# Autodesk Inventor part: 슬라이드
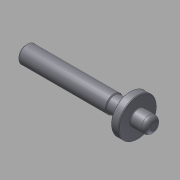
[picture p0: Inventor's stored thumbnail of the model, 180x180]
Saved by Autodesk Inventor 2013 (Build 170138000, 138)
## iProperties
Company: 한국ATC센터
Created: 2015-12
Part Number: 슬라이드
Document SubType Name: Modeling
Designer: mdu
Density: 7.86 g/cm^3
Mass: 68.0563 g
Surface Area: 34.7349 cm^2
Volume: 8.65856 cm^3
Material: 강철, 연강
Author: mdu
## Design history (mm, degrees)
sketch "스케치1"
  geometry: L1 (-35, 0)-(35, 0); L2 (35, 0)-(35, 12); L3 (35, 12)-(30, 12); L4 (30, 12)-(30, 5); L5 (30, 5)-(20.5, 5); L6 (20.5, 5)-(20, 5.5); L7 (20, 5.5)-(-35, 5.5); L8 (-35, 5.5)-(-35, 0); 1 further point
  constraints: 16 end point, 4 parallel, 2 midpoint, 2 perpendicular, 1 horizontal
  dimensions: "d0" = 70 distance of L1.start L1.end; "d1" = 11 diameter of L7 L1; "d2" = 24 diameter of L3 L1; "d3" = 5 distance of L2.end L3.end; "d4" = 10 diameter of L5 L1; "d5" = 135 deg angle of L6 L5; "d6" = 15 distance from line of L2 L6.end
revolve "회전1" sketch "스케치1" stored, may be unused: angle "d7" = 90 deg
chamfer "모따기1" distance "d8" = 1; stored, may be unused: second distance "d9" = 2, angle "d10" = 45 deg
fillet "모깎기1" dims "d11" = 0.5
sketch "스케치2"
  geometry: C1 r 11.5 at (0, 0) reference; C2 r 5 at (0, 0)
  constraints: 1 centre point, 1 coincident
  dimensions: "d12" = 10 diameter of C2
extrude "돌출1" join sketch "스케치2" distance "d13" = 10; taper "d14" = 0 deg
fillet "모깎기2" dims "d16" = 0.5
fillet "모깎기3" dims "d17" = 3
node "솔리드1"
